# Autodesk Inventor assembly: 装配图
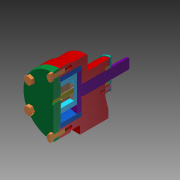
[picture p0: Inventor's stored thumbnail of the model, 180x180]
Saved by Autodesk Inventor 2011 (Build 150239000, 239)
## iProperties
Created: 2014-03
Part Number: 装配图
Document SubType Name: Assembly
Designer: Administrator
Author: Administrator
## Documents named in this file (14)
- C:\Users\頔。\Desktop\机械制图\第二册模型\第二本习题模型\给周迪的模型\6-6三元子泵\装配图.iam
- C:\Users\頔。\Desktop\机械制图\第二册模型\第二本习题模型\给周迪的模型\6-6三元子泵\泵体.ipt
- C:\Users\頔。\Desktop\机械制图\第二册模型\第二本习题模型\给周迪的模型\6-6三元子泵\泵盖.ipt
- C:\Users\頔。\Desktop\机械制图\第二册模型\第二本习题模型\给周迪的模型\6-6三元子泵\衬套.ipt
- C:\Users\頔。\Desktop\机械制图\第二册模型\第二本习题模型\给周迪的模型\6-6三元子泵\大滑块.ipt
- C:\Users\頔。\Desktop\机械制图\第二册模型\第二本习题模型\给周迪的模型\6-6三元子泵\垫片.ipt
- C:\Users\頔。\Desktop\机械制图\第二册模型\第二本习题模型\给周迪的模型\6-6三元子泵\螺钉M4×8.ipt
- C:\Users\頔。\Desktop\机械制图\第二册模型\第二本习题模型\给周迪的模型\6-6三元子泵\螺钉M6×16.ipt
- C:\Users\頔。\Desktop\机械制图\第二册模型\第二本习题模型\给周迪的模型\6-6三元子泵\密封环.ipt
- C:\Users\頔。\Desktop\机械制图\第二册模型\第二本习题模型\给周迪的模型\6-6三元子泵\销钉3m6×14.ipt
- C:\Users\頔。\Desktop\机械制图\第二册模型\第二本习题模型\给周迪的模型\6-6三元子泵\小滑块.ipt
- C:\Users\頔。\Desktop\机械制图\第二册模型\第二本习题模型\给周迪的模型\6-6三元子泵\小轴.ipt
- C:\Users\頔。\Desktop\机械制图\第二册模型\第二本习题模型\给周迪的模型\6-6三元子泵\压盖.ipt
- C:\Users\頔。\Desktop\机械制图\第二册模型\第二本习题模型\给周迪的模型\6-6三元子泵\转子轴.ipt
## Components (20 placed, 13 different names)
1. 泵体:1 — 插入:1, 配合:1, 配合:2, 配合:14, 配合:15, 表面齐平:1, 配合:25, 配合:26, 配合:27, 配合:30
2. 泵盖:1 — 配合:28, 配合:29, 配合:30, 配合:31, 表面齐平:2, 配合:32, 配合:33, 配合:34, 配合:35, 配合:36, 配合:37, 配合:38, 配合:39, 配合:40, 配合:41, 配合:42, 配合:43
3. 衬套:1 — 配合:2, 配合:6, 配合:7, 配合:10
4. 大滑块:1 — 配合:3, 配合:4, 配合:5, 配合:8, 配合:9, 配合:10, 配合:12
5. 垫片:1 — 配合:25, 配合:26, 配合:27, 配合:28, 配合:29
6. 螺钉M4×8:1 — 配合:17, 配合:18, 配合:19, 配合:20
7. 螺钉M6×16:1 — 配合:32, 配合:34
8. 密封环:1 — 表面齐平:1
9. 销钉3m6×14:1 — 配合:31, 表面齐平:2
10. 小滑块:1 — 配合:8, 配合:9, 配合:11, 配合:13
11. 小轴:1 — 配合:12, 配合:13
12. 压盖:1 — 配合:14, 配合:15, 配合:16, 配合:17, 配合:18, 配合:19, 配合:20, 配合:21, 配合:22, 配合:23, 配合:24
13. 转子轴:1 — 插入:1, 配合:1, 配合:3, 配合:4, 配合:5, 配合:6, 配合:7, 配合:11, 配合:16
14. 螺钉M4×8:2 — 配合:23, 配合:24
15. 螺钉M4×8:3 — 配合:21, 配合:22
16. 螺钉M6×16:2 — 配合:37, 配合:42
17. 螺钉M6×16:3 — 配合:33, 配合:35
18. 螺钉M6×16:4 — 配合:39, 配合:41
19. 螺钉M6×16:5 — 配合:36, 配合:43
20. 螺钉M6×16:6 — 配合:38, 配合:40
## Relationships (46: Mate 43, Flush 2, Insert 1)
- 插入:1 [Insert]: 泵体:1 ↔ 转子轴:1
- 配合:1 [Mate]: 泵体:1 ↔ 转子轴:1
- 配合:2 [Mate]: 泵体:1 ↔ 衬套:1
- 配合:3 [Mate]: 大滑块:1 ↔ 转子轴:1
- 配合:4 [Mate]: 大滑块:1 ↔ 转子轴:1
- 配合:5 [Mate]: 大滑块:1 ↔ 转子轴:1
- 配合:6 [Mate]: 衬套:1 ↔ 转子轴:1
- 配合:7 [Mate]: 衬套:1 ↔ 转子轴:1
- 配合:8 [Mate]: 大滑块:1 ↔ 小滑块:1
- 配合:9 [Mate]: 大滑块:1 ↔ 小滑块:1
- 配合:10 [Mate]: 衬套:1 ↔ 大滑块:1
- 配合:11 [Mate]: 小滑块:1 ↔ 转子轴:1
- 配合:12 [Mate]: 大滑块:1 ↔ 小轴:1
- 配合:13 [Mate]: 小滑块:1 ↔ 小轴:1
- 配合:14 [Mate]: 泵体:1 ↔ 压盖:1
- 配合:15 [Mate]: 泵体:1 ↔ 压盖:1
- 配合:16 [Mate]: 压盖:1 ↔ 转子轴:1
- 表面齐平:1 [Flush]: 泵体:1 ↔ 密封环:1
- 配合:17 [Mate]: 螺钉M4×8:1 ↔ 压盖:1
- 配合:18 [Mate]: 螺钉M4×8:1 ↔ 压盖:1
- 配合:19 [Mate]: 螺钉M4×8:1 ↔ 压盖:1
- 配合:20 [Mate]: 螺钉M4×8:1 ↔ 压盖:1
- 配合:21 [Mate]: 压盖:1 ↔ 螺钉M4×8:3
- 配合:22 [Mate]: 压盖:1 ↔ 螺钉M4×8:3
- 配合:23 [Mate]: 压盖:1 ↔ 螺钉M4×8:2
- 配合:24 [Mate]: 压盖:1 ↔ 螺钉M4×8:2
- 配合:25 [Mate]: 泵体:1 ↔ 垫片:1
- 配合:26 [Mate]: 泵体:1 ↔ 垫片:1
- 配合:27 [Mate]: 泵体:1 ↔ 垫片:1
- 配合:28 [Mate]: 泵盖:1 ↔ 垫片:1
- 配合:29 [Mate]: 泵盖:1 ↔ 垫片:1
- 配合:30 [Mate]: 泵体:1 ↔ 泵盖:1
- 配合:31 [Mate]: 泵盖:1 ↔ 销钉3m6×14:1
- 表面齐平:2 [Flush]: 泵盖:1 ↔ 销钉3m6×14:1
- 配合:32 [Mate]: 泵盖:1 ↔ 螺钉M6×16:1
- 配合:33 [Mate]: 泵盖:1 ↔ 螺钉M6×16:3
- 配合:34 [Mate]: 泵盖:1 ↔ 螺钉M6×16:1
- 配合:35 [Mate]: 泵盖:1 ↔ 螺钉M6×16:3
- 配合:36 [Mate]: 泵盖:1 ↔ 螺钉M6×16:5
- 配合:37 [Mate]: 泵盖:1 ↔ 螺钉M6×16:2
- 配合:38 [Mate]: 泵盖:1 ↔ 螺钉M6×16:6
- 配合:39 [Mate]: 泵盖:1 ↔ 螺钉M6×16:4
- 配合:40 [Mate]: 泵盖:1 ↔ 螺钉M6×16:6
- 配合:41 [Mate]: 泵盖:1 ↔ 螺钉M6×16:4
- 配合:42 [Mate]: 泵盖:1 ↔ 螺钉M6×16:2
- 配合:43 [Mate]: 泵盖:1 ↔ 螺钉M6×16:5
